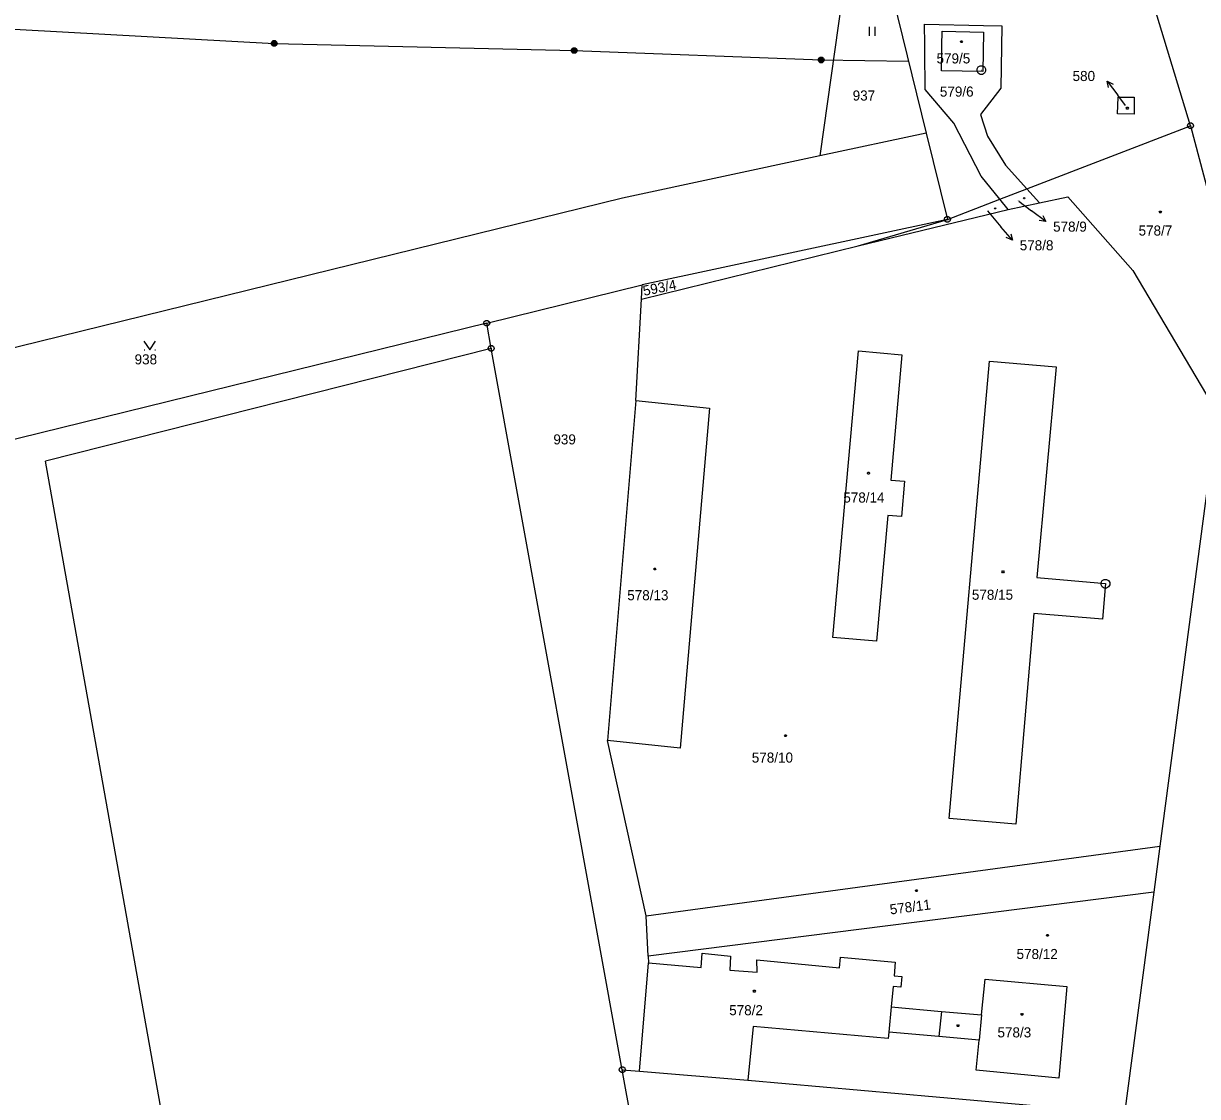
# Model space of a CAD drawing. Extents: x -812394 to -807601, y -1013098 to -1009266.
# Drawn here: x -809265.1 to -809067, y -1011988.8 to -1011807.7 of the extents above; entities that cross this region are included whole.
import ezdxf

# ---------------------------------------------------------------- set-up
doc = ezdxf.new("R2010")
doc.units = 0
for name, color, linetype in [('KN_HRANICE', 7, 'Continuous'), ('KN_KULTURY', 7, 'Continuous'), ('KN_MEZNIKY', 7, 'Continuous'), ('KN_PARCELY', 7, 'Continuous'), ('KN_SLUCKY', 7, 'Continuous'), ('KN_VEDENI', 7, 'Continuous')]:
    doc.layers.add(name, color=color, linetype=linetype)

# ---------------------------------------------------------------- blocks, each defined once
blk = doc.blocks.new('101')
blk.add_line((-0.05, 0), (0.05, 0))
blk.add_lwpolyline([(0.19, 0.72), (0.53, 0.53), (0.72, 0.19), (0.72, -0.2), (0.53, -0.54), (0.19, -0.73), (-0.2, -0.73), (-0.54, -0.54), (-0.73, -0.2), (-0.73, 0.19), (-0.54, 0.53), (-0.2, 0.72), (0.19, 0.72)])
blk = doc.blocks.new('306')
for p, q in [((-0.5, 1.5), (-0.5, 0)), ((0.5, 0), (0.5, 1.5))]:
    blk.add_line(p, q)
blk = doc.blocks.new('314')
for p, q in [((-0.95, 0), (-0.85, 0)), ((0.85, 0), (0.95, 0))]:
    blk.add_line(p, q)
blk.add_lwpolyline([(-1, 1.5), (0, 0), (1, 1.5)])
blk = doc.blocks.new('NAHRADNI_SYMBOL')
blk.add_lwpolyline([(0.09, 0.15), (0.18, 0), (0.09, -0.15), (-0.09, -0.15), (-0.18, 0), (-0.09, 0.15), (0.09, 0.15)])
blk = doc.blocks.new('10292')
blk.add_line((0, 3), (0, 0))
blk.add_lwpolyline([(-0.5, 2), (0, 3), (0.5, 2)])
blk = doc.blocks.new('402')
blk.add_lwpolyline([(0.09, 0.15), (0.18, 0), (0.09, -0.15), (-0.09, -0.15), (-0.18, 0), (-0.09, 0.15), (0.09, 0.15)])
blk = doc.blocks.new('105')
blk.add_line((-0.12, 0), (0.12, 0))
blk.add_lwpolyline([(0.15, 0.48), (0.4, 0.3), (0.5, 0.01), (0.4, -0.28), (0.15, -0.46), (-0.16, -0.46), (-0.41, -0.28), (-0.51, 0.01), (-0.41, 0.3), (-0.16, 0.48), (0.15, 0.48)])
blk = doc.blocks.new('601')
blk.add_lwpolyline([(-0.15, 0.48), (0.16, 0.48), (0.41, 0.3), (0.51, 0.01), (0.41, -0.28), (0.16, -0.46), (-0.15, -0.46), (-0.4, -0.28), (-0.5, 0.01), (-0.4, 0.3), (-0.15, 0.48), (-0.12, 0.44), (0.12, 0.44), (0.28, 0.36), (-0.28, 0.36), (-0.36, 0.28), (0.36, 0.28), (0.36, 0.2), (-0.36, 0.2), (-0.4, 0.12), (0.4, 0.12), (0.44, 0.04), (-0.44, 0.04), (-0.44, -0.04), (0.44, -0.04), (0.41, -0.12), (-0.4, -0.12), (-0.39, -0.2), (0.42, -0.2), (0.37, -0.28), (-0.35, -0.28), (-0.27, -0.36), (0.29, -0.36), (0.18, -0.44), (-0.16, -0.44)])

msp = doc.modelspace()

# ---------------------------------------------------------------- linework, layer by layer
at = {"layer": 'KN_HRANICE'}
for p, q in [((-809068.2, -1011824.99), (-809084.06, -1011773.13)), ((-809125.69, -1011793.95), (-809130.74, -1011830.07)), ((-809120.59, -1011794.42), (-809112.8, -1011826.22)), ((-809113.05, -1011811.37), (-809113.08, -1011807.88)), ((-809113.08, -1011807.88), (-809103.13, -1011808.08)), ((-809103.13, -1011808.08), (-809100.05, -1011808.14)), ((-809100.05, -1011808.14), (-809100.21, -1011818.65)), ((-809110.16, -1011811.48), (-809110.12, -1011809.06)), ((-809110.12, -1011809.06), (-809103.14, -1011809.22)), ((-809103.14, -1011809.22), (-809103.26, -1011815.85)), ((-809113.04, -1011812.38), (-809113.05, -1011811.37)), ((-809112.98, -1011818.85), (-809113.04, -1011812.38)), ((-809110.18, -1011812.48), (-809110.16, -1011811.48)), ((-809110.24, -1011815.74), (-809110.18, -1011812.48)), ((-809103.26, -1011815.85), (-809110.24, -1011815.74)), ((-809108.12, -1011824.53), (-809112.98, -1011818.85)), ((-809100.21, -1011818.65), (-809103.62, -1011823.1)), ((-809080.52, -1011823), (-809080.41, -1011820.15)), ((-809080.41, -1011820.15), (-809077.71, -1011820.19)), ((-809077.71, -1011820.19), (-809077.75, -1011823.05)), ((-809103.62, -1011823.1), (-809102.48, -1011826.76)), ((-809077.75, -1011823.05), (-809080.52, -1011823)), ((-809112.8, -1011826.22), (-809130.74, -1011830.07)), ((-809112.8, -1011826.22), (-809109.23, -1011840.79)), ((-809103.55, -1011833.5), (-809108.12, -1011824.53)), ((-809095.84, -1011835.63), (-809068.2, -1011824.99)), ((-809068.2, -1011824.99), (-809061.74, -1011849.58)), ((-809102.48, -1011826.76), (-809099.43, -1011831.65)), ((-809130.74, -1011830.07), (-809164.04, -1011837.22)), ((-809099.43, -1011831.65), (-809095.84, -1011835.63)), ((-809100.4, -1011837.39), (-809103.55, -1011833.5)), ((-809100.4, -1011837.39), (-809095.84, -1011835.63)), ((-809095.84, -1011835.63), (-809093.72, -1011837.98)), ((-809164.04, -1011837.22), (-809345.17, -1011881.72)), ((-809109.23, -1011840.79), (-809100.4, -1011837.39)), ((-809099, -1011839.11), (-809100.4, -1011837.39)), ((-809099, -1011839.11), (-809093.72, -1011837.98)), ((-809093.72, -1011837.98), (-809088.93, -1011836.97)), ((-809088.93, -1011836.97), (-809077.97, -1011849.39)), ((-809124.28, -1011845.23), (-809099, -1011839.11)), ((-809109.23, -1011840.79), (-809160.7, -1011851.85)), ((-809124.28, -1011845.23), (-809109.23, -1011840.79)), ((-809160.83, -1011854.23), (-809124.28, -1011845.23)), ((-809077.97, -1011849.39), (-809063.7, -1011873.44)), ((-809186.95, -1011858.3), (-809160.7, -1011851.85)), ((-809160.83, -1011854.23), (-809160.7, -1011851.85)), ((-809161.77, -1011871.36), (-809160.83, -1011854.23)), ((-809186.95, -1011858.3), (-809342.02, -1011896.39)), ((-809186.18, -1011862.56), (-809186.95, -1011858.3)), ((-809186.18, -1011862.56), (-809261.37, -1011881.55)), ((-809164.07, -1011984.25), (-809186.18, -1011862.56)), ((-809128.55, -1011911.3), (-809124.24, -1011862.99)), ((-809124.24, -1011862.99), (-809116.9, -1011863.65)), ((-809116.9, -1011863.65), (-809118.76, -1011884.76)), ((-809108.95, -1011941.85), (-809102.15, -1011864.7)), ((-809102.15, -1011864.7), (-809090.9, -1011865.67)), ((-809090.9, -1011865.67), (-809094.12, -1011901.22)), ((-809161.77, -1011871.36), (-809166.58, -1011928.68)), ((-809161.77, -1011871.36), (-809149.38, -1011872.63)), ((-809149.38, -1011872.63), (-809154.29, -1011929.97)), ((-809063.7, -1011873.44), (-809073.39, -1011946.52)), ((-809228.83, -1012064.27), (-809261.37, -1011881.55)), ((-809118.76, -1011884.76), (-809116.47, -1011884.97)), ((-809116.47, -1011884.97), (-809117, -1011890.94)), ((-809119.3, -1011890.74), (-809121.18, -1011911.95)), ((-809117, -1011890.94), (-809119.3, -1011890.74)), ((-809094.12, -1011901.22), (-809082.56, -1011902.24)), ((-809082.56, -1011902.24), (-809083.08, -1011908.25)), ((-809094.64, -1011907.27), (-809097.69, -1011942.84)), ((-809083.08, -1011908.25), (-809094.64, -1011907.27)), ((-809121.18, -1011911.95), (-809128.55, -1011911.3)), ((-809160.06, -1011958.27), (-809166.58, -1011928.68)), ((-809154.29, -1011929.97), (-809166.58, -1011928.68)), ((-809097.69, -1011942.84), (-809108.95, -1011941.85)), ((-809160.06, -1011958.27), (-809073.39, -1011946.52)), ((-809073.39, -1011946.52), (-809074.42, -1011954.31)), ((-809074.42, -1011954.31), (-809159.72, -1011965.09)), ((-809074.42, -1011954.31), (-809079.37, -1011991.64)), ((-809159.72, -1011965.09), (-809160.06, -1011958.27)), ((-809150.77, -1011967), (-809150.6, -1011964.6)), ((-809150.6, -1011964.6), (-809145.84, -1011965.06)), ((-809161.18, -1011984.49), (-809159.66, -1011966.19)), ((-809159.72, -1011965.09), (-809159.66, -1011966.19)), ((-809159.66, -1011966.19), (-809150.77, -1011967)), ((-809145.84, -1011965.06), (-809145.95, -1011967.43)), ((-809141.35, -1011967.76), (-809141.36, -1011965.71)), ((-809141.36, -1011965.71), (-809127.42, -1011967.04)), ((-809127.42, -1011967.04), (-809127.27, -1011965.28)), ((-809127.27, -1011965.28), (-809118.02, -1011966.1)), ((-809118.02, -1011966.1), (-809118.23, -1011968.41)), ((-809145.95, -1011967.43), (-809141.35, -1011967.76)), ((-809118.23, -1011968.41), (-809116.93, -1011968.53)), ((-809116.93, -1011968.53), (-809117.08, -1011970.31)), ((-809118.4, -1011970.2), (-809118.71, -1011973.66)), ((-809117.08, -1011970.31), (-809118.4, -1011970.2)), ((-809103.47, -1011974.99), (-809102.85, -1011968.95)), ((-809102.85, -1011968.95), (-809089.07, -1011970.21)), ((-809089.07, -1011970.21), (-809090.44, -1011985.64)), ((-809118.71, -1011973.66), (-809110.23, -1011974.41)), ((-809110.23, -1011974.41), (-809110.65, -1011978.63)), ((-809110.23, -1011974.41), (-809103.47, -1011974.99)), ((-809142.02, -1011976.94), (-809142.88, -1011986.01)), ((-809119.2, -1011978.96), (-809142.02, -1011976.94)), ((-809119.1, -1011977.88), (-809119.2, -1011978.96)), ((-809110.65, -1011978.63), (-809119.1, -1011977.88)), ((-809103.87, -1011979.23), (-809110.65, -1011978.63)), ((-809104.35, -1011984.34), (-809103.87, -1011979.23)), ((-809156.68, -1012024.93), (-809164.07, -1011984.25)), ((-809164.07, -1011984.25), (-809161.18, -1011984.49)), ((-809161.18, -1011984.49), (-809142.88, -1011986.01)), ((-809090.44, -1011985.64), (-809104.35, -1011984.34)), ((-809142.88, -1011986.01), (-809079.37, -1011991.64))]:
    msp.add_line(p, q, dxfattribs=at)
at = {"layer": 'KN_PARCELY'}
for p, q in [((-809079.16, -1011821.56), (-809080.45, -1011819.85)), ((-809097.16, -1011837.7), (-809095.02, -1011839.34)), ((-809102.48, -1011839.36), (-809100.21, -1011842.02))]:
    msp.add_line(p, q, dxfattribs=at)
at = {"layer": 'KN_SLUCKY'}
for p, q in [((-809118.71, -1011973.66), (-809119.1, -1011977.88)), ((-809103.47, -1011974.99), (-809103.87, -1011979.23))]:
    msp.add_line(p, q, dxfattribs=at)
at = {"layer": 'KN_VEDENI'}
msp.add_lwpolyline([(-809530.59, -1011529.94), (-809514.36, -1011553.41), (-809497.68, -1011576.04), (-809445.29, -1011648.83), (-809392.83, -1011722.03), (-809339.15, -1011792.47), (-809315.72, -1011805.98), (-809222.8, -1011811.11), (-809172.21, -1011812.31), (-809130.54, -1011813.9), (-809115.78, -1011814.07)], dxfattribs=at)

# ---------------------------------------------------------------- block references
at = {"layer": 'KN_KULTURY'}
for name, p in [('306', (-809121.91, -1011809.83)), ('402', (-809106.86, -1011810.79)), ('402', (-809078.87, -1011822.02)), ('NAHRADNI_SYMBOL', (-809073.31, -1011839.55)), ('314', (-809243.8, -1011862.82)), ('402', (-809122.54, -1011883.61)), ('402', (-809158.6, -1011899.76)), ('402', (-809099.86, -1011900.25)), ('NAHRADNI_SYMBOL', (-809136.53, -1011927.88)), ('NAHRADNI_SYMBOL', (-809114.45, -1011954.04)), ('NAHRADNI_SYMBOL', (-809092.34, -1011961.57)), ('402', (-809141.81, -1011970.99)), ('402', (-809096.65, -1011974.91)), ('402', (-809107.44, -1011976.81))]:
    msp.add_blockref(name, p, dxfattribs=at)
at = {"layer": 'KN_KULTURY', "xscale": 0.67, "yscale": 0.67}
for p in [(-809096.26, -1011837.22), (-809101.19, -1011838.93)]:
    msp.add_blockref('NAHRADNI_SYMBOL', p, dxfattribs=at)
at = {"layer": 'KN_MEZNIKY'}
for name, p in [('101', (-809103.5, -1011815.6)), ('105', (-809068.2, -1011824.99)), ('105', (-809109.23, -1011840.79)), ('105', (-809186.95, -1011858.3)), ('105', (-809186.18, -1011862.56)), ('101', (-809082.56, -1011902.26)), ('105', (-809164.07, -1011984.25))]:
    msp.add_blockref(name, p, dxfattribs=at)
at = {"layer": 'KN_PARCELY'}
for p, rotation in [((-809080.45, -1011819.85), 37.013073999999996), ((-809095.02, -1011839.34), -127.43643100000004), ((-809100.21, -1011842.02), -139.64043199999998)]:
    msp.add_blockref('10292', p, dxfattribs=dict(at, rotation=rotation))
at = {"layer": 'KN_VEDENI'}
for p in [(-809222.8, -1011811.11), (-809172.21, -1011812.31), (-809130.54, -1011813.9)]:
    msp.add_blockref('601', p, dxfattribs=at)

# ---------------------------------------------------------------- texts
at = {"layer": 'KN_PARCELY'}
for s, height, p in [('579/5', 1.7, (-809111.06, -1011814.48)), ('580', 1.7, (-809088.11, -1011817.45)), ('579/6', 1.7, (-809110.5, -1011820.08)), ('937', 1.7, (-809125.21, -1011820.74)), ('580', 0.1, (-809079.3, -1011821.56)), ('578/9', 0.1, (-809097.4, -1011837.7)), ('578/8', 0.1, (-809102.72, -1011839.36)), ('578/9', 1.7, (-809091.4, -1011842.86)), ('578/7', 1.7, (-809076.98, -1011843.52)), ('578/8', 1.7, (-809097.03, -1011846.01)), ('938', 1.7, (-809246.35, -1011865.25)), ('939', 1.7, (-809175.7, -1011878.75)), ('578/14', 1.7, (-809126.79, -1011888.56)), ('578/13', 1.7, (-809163.24, -1011905.04)), ('578/15', 1.7, (-809105.1, -1011904.96)), ('578/10', 1.7, (-809142.23, -1011932.43)), ('578/12', 1.7, (-809097.56, -1011965.57)), ('578/2', 1.7, (-809146.04, -1011975.05)), ('578/3', 1.7, (-809100.78, -1011978.79))]:
    msp.add_text(s, height=height, dxfattribs=at).set_placement(p)
for s, rotation, p in [('593/4', 11.23, (-809160.41, -1011853.7)), ('578/11', 7.219, (-809118.84, -1011958.06))]:
    msp.add_text(s, height=1.7, rotation=rotation, dxfattribs=at).set_placement(p)

doc.saveas('drawing.dxf')
